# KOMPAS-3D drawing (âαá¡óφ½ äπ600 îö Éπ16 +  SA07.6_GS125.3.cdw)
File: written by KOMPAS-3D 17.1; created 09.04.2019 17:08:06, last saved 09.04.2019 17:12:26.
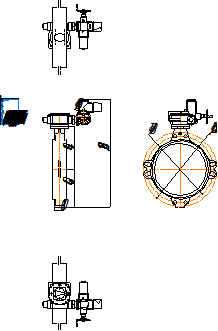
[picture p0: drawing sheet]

Sheet 1: A4, portrait

Title block, sheet 1: name: Гранвэл Ду600 МФ Ру16 + / SA07.6_GS125.3; material: Внимание! Данный продукт является объектом авторского права ООО «Торговый Дом АДЛ». / Запрещается изменение, копирование, распространение / (в том числе путем копирования на другие сайты и ресурсы в Интернете) / или любое иное использование информации и объектов без предварительного / согласия правообладателя (ООО «Торговый Дом АДЛ»).; mass: 468,53; sheets: 1; organisation: ООО "Торговый дом АДЛ"; sheet format: A4

Views: Вид 1, Проекционный вид 2, Проекционный вид 3, Проекционный вид 4
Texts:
  user
Dimensions and other numbers on the sheet: 494; 440; 110; 1246,8; 160; 855,86; 770; 1:1; 1; 468,53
